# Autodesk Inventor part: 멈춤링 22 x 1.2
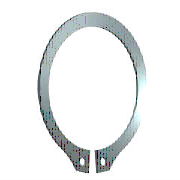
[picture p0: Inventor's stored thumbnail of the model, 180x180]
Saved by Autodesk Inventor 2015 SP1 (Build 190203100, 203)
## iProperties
IsCustomPart: 0
Created: 2009-02
Part Number: 멈춤링 22 x 1.2
Material: Steel, Mild
Description: 리테이닝 링(C형)
Document SubType Name: Modeling
Standard: KS B 1336
Designer: SeoGD™
Standards Organization: KS
Language: ko-KR
Size Designation: 22 x 1.2
Categories: <MemberInstance><Categories><Category DisplayName="샤프트 부품" InternalName="7f7aeb1f-a693-4053-b835-cee3144e0d98" Mnemonic="SHFT"><Category DisplayName="써클립" Inter
Density: 7.86 g/cm^3
Appearance: Metal-Steel
Mass: 1.8286 g
Surface Area: 5.91219 cm^2
Volume: 0.232646 cm^3
Author: SeoGD™
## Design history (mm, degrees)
sketch "스케치1"
  geometry: L1 (-6, 0)-(6, 0) reference; L2 (0, 20.189)-(0, -80.536) reference; L3 (-48.09, 0)-(48.09, 0) reference; L4 (-0.5, -21.488)-(-0.5, -25.588); L5 (-0.5, -6.54)-(-0.5, -13.29); L6 (-2.795, 2.7)-(3.672, 2.7); L7 (0.5, -6.54)-(0.5, -13.29); L8 (0.5, -21.488)-(0.5, -25.588); C1 r 1 at (-2, -23.437); C2 r 1 at (2, -23.437); A1 r 10.5 centre (0, -11) between (0.5, -21.488) and (-0.5, -21.488); A2 r 13.025 centre (0, -10.325) between (5.149, -22.289) and (-5.149, -22.289); A3 r 14.597 centre (0, -11) between (-2.318, -25.411) and (-0.5, -25.588); A4 r 2 centre (-2, -23.437) between (-3.97, -23.781) and (-2.318, -25.411); A5 r 2 centre (-5.94, -24.126) between (-3.97, -23.781) and (-5.149, -22.289); A6 r 2 centre (5.94, -24.126) between (5.149, -22.289) and (3.97, -23.781); A7 r 2 centre (2, -23.437) between (2.318, -25.411) and (3.97, -23.781); A8 r 14.597 centre (0, -11) between (0.5, -25.588) and (2.318, -25.411)
  constraints: 16 point on circle, 12 end point, 10 centre point, 9 symmetric about line, 5 point on line, 4 tangent, 3 coincident, 2 horizontal, 1 perpendicular, 1 vertical, 5 other
  dimensions: "d0" = 21 diameter of A1 (= ND); "d1" = 4.1 distance of L4.end L4.start (= SRB2); "d6" = 0.5 distance between parallel lines of L2 L5 (= 0.25 x SD5); "d7" = 2.7 distance between parallel lines of L6 L3 (= SRB1); "d8" = 0.675 distance of A1.centre A2.centre (= 0.25 x SRB1); "d9" = 2 radius of A4 (= SD5); "d10" = 2 radius of A5 (= SD5); "d11" = 1.5 distance from line of L4 A4.centre (= 0.75 x SD5); "d12" = 2 diameter of C1 (= SD5); "d13" = 2 diameter of C2 (= SD5); "d14" = 11 distance from line of A1.centre L1 (= 0.5 x WD)
extrude "본체" new body sketch "스케치1" distance "d2" = 1.2 (= SD); taper "d3" = 0 deg
workaxis "Work Axis1"
workplane "Work Plane1"
body "Solid1"
other parameters: "WD" = 22 (= WDMIN) [user parameter; used in 1 equation term], "SD" = 1.2 [user parameter; used in 1 equation term], "SRB1" = 2.7 [user parameter; used in 2 equation terms], "ND" = 21 [user parameter; used in 1 equation term], "SRB2" = 4.1 [user parameter; used in 1 equation term], "SD5" = 2 [user parameter; used in 6 equation terms], "d15" = 0, "d16" = 0, "d17" = 0, "d41" = 0, "d42" = 0, "WDMIN" = 22 [user parameter; used in 1 equation term], "SD3" = 20.5 [user parameter], "WDMAX" = 24 [user parameter]
